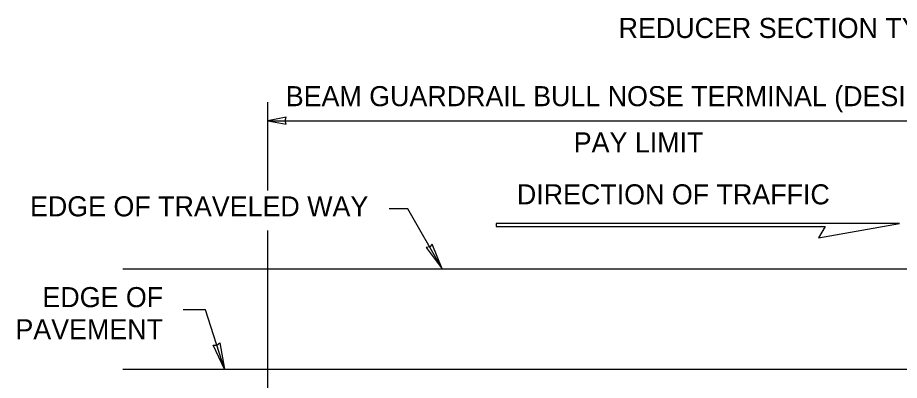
# Model space of a CAD drawing. Extents: x 1312564.5 to 1312581.5, y 1207298.4 to 1207309.4.
# Drawn here: x 1312575.137 to 1312578.654, y 1207305.558 to 1207307.004 of the extents above; entities that cross this region are included whole.
import ezdxf

# ---------------------------------------------------------------- set-up
doc = ezdxf.new("R2010")
doc.units = 0
for name, color, linetype in [('Level 15', 7, 'Continuous'), ('Level 20', 7, 'Continuous'), ('Level 3', 7, 'Continuous'), ('Level 4', 7, 'Continuous'), ('Level 44', 7, 'Continuous')]:
    doc.layers.add(name, color=color, linetype=linetype)

msp = doc.modelspace()

# ---------------------------------------------------------------- linework, layer by layer
at = {"layer": 'Level 15'}
for p, q in [((1312576.6932, 1207306.2413), (1312576.6195, 1207306.2413)), ((1312576.8308, 1207306.0031), (1312576.6932, 1207306.2413)), ((1312575.8868, 1207305.8387), (1312575.7968, 1207305.8387)), ((1312575.962, 1207305.6025), (1312575.8868, 1207305.8387))]:
    msp.add_line(p, q, dxfattribs=at)
for points in [[(1312576.1354, 1207306.3151), (1312576.1354, 1207306.6666)], [(1312576.1354, 1207306.5929), (1312579.106, 1207306.5929)], [(1312576.1354, 1207304.7936), (1312576.1354, 1207306.1548)]]:
    msp.add_lwpolyline(points, dxfattribs=at)
for points in [[(1312576.1354, 1207306.5929), (1312576.2079, 1207306.5787), (1312576.2045, 1207306.5929), (1312576.2079, 1207306.6071)], [(1312576.8308, 1207306.0031), (1312576.7901, 1207306.1011), (1312576.7806, 1207306.09), (1312576.7663, 1207306.0873)], [(1312575.962, 1207305.6025), (1312575.917, 1207305.6986), (1312575.9315, 1207305.6981), (1312575.9432, 1207305.7069)]]:
    msp.add_lwpolyline(points, close=True, dxfattribs=at)
at = {"layer": 'Level 3'}
msp.add_line((1312575.556, 1207305.6025), (1312580.9146, 1207305.6025), dxfattribs=at)
msp.add_lwpolyline([(1312577.0456, 1207306.1714), (1312578.3577, 1207306.1714), (1312578.3314, 1207306.126), (1312578.6538, 1207306.1828), (1312577.0456, 1207306.1828)], close=True, dxfattribs=at)
at = {"layer": 'Level 44'}
msp.add_line((1312575.556, 1207306.0031), (1312580.9267, 1207306.0031), dxfattribs=at)

# ---------------------------------------------------------------- texts
at = {"layer": 'Level 20'}
for s, p in [('BEAM GUARDRAIL BULL NOSE TERMINAL (DESIGN 2)', (1312576.2065, 1207306.6509)), ('PAY LIMIT', (1312577.3551, 1207306.4666)), ('DIRECTION OF TRAFFIC', (1312577.1284, 1207306.2595)), ('EDGE OF', (1312575.2359, 1207305.8497)), (' PAVEMENT', (1312575.0985, 1207305.7217))]:
    msp.add_text(s, height=0.08, dxfattribs=at).set_placement(p)
msp.add_text('EDGE OF TRAVELED WAY', height=0.08, rotation=360, dxfattribs=at).set_placement((1312575.1864, 1207306.2117))
at = {"layer": 'Level 4'}
msp.add_text('REDUCER SECTION TYPE B', height=0.08, dxfattribs=at).set_placement((1312577.5341, 1207306.9227))

doc.saveas('drawing.dxf')
